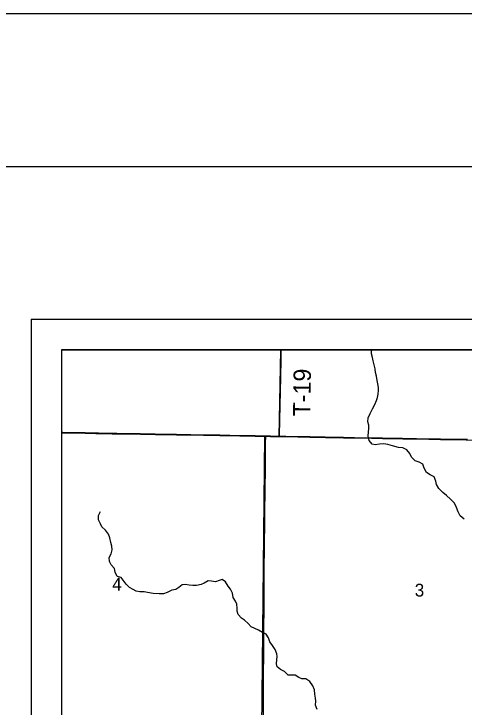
# Model space of a CAD drawing. Extents: x 0 to 34, y 0 to 22.
# Drawn here: x 1.944 to 3.417, y 19.729 to 22 of the extents above; entities that cross this region are included whole.
import ezdxf

# ---------------------------------------------------------------- set-up
doc = ezdxf.new("R2010")
doc.units = 0
for name, color, linetype in [('GM_X_Corporation', 7, 'Continuous'), ('GM_X_County_Road', 7, 'Continuous'), ('GM_X_Minor_River', 7, 'Continuous'), ('GM_X_Section_Text', 7, 'Continuous'), ('GM_X_Township_Road', 7, 'Continuous'), ('GM_X_Township_Road_Text', 7, 'Continuous'), ('SH_Border', 7, 'Continuous'), ('SH_Cut_Line', 7, 'Continuous'), ('SH_Data', 7, 'Continuous')]:
    doc.layers.add(name, color=color, linetype=linetype)

msp = doc.modelspace()

# ---------------------------------------------------------------- linework, layer by layer
at = {"layer": 'GM_X_Corporation'}
for points in [[(8.9, 20.9), (2.1, 20.9), (2.1, 14.6217)], [(5.8292, 20.9), (2.1, 20.9), (2.1, 20.6285), (2.1044, 20.6284), (2.1771, 20.6273), (2.2119, 20.6266), (2.2647, 20.6256), (2.3027, 20.6249), (2.3574, 20.6241), (2.4065, 20.6233), (2.4755, 20.6222), (2.5209, 20.6212), (2.5638, 20.6206), (2.6178, 20.6196), (2.6831, 20.6184), (2.7328, 20.6177), (2.7675, 20.617), (2.7831, 20.6167), (2.8132, 20.6163), (2.8341, 20.616), (2.8727, 20.6152), (2.9124, 20.6145), (2.9628, 20.6136), (3.0218, 20.6125), (3.0585, 20.6118), (3.1138, 20.6107), (3.1499, 20.6101), (3.2158, 20.6091), (3.2611, 20.6084), (3.3078, 20.6075), (3.3395, 20.6068), (3.3867, 20.6062), (3.4277, 20.6055)], [(3.4277, 20.6055), (3.3867, 20.6062), (3.3395, 20.6068), (3.3078, 20.6075), (3.2611, 20.6084), (3.2158, 20.6091), (3.1499, 20.6101), (3.1138, 20.6107), (3.0585, 20.6118), (3.0218, 20.6125), (2.9628, 20.6136), (2.9124, 20.6145), (2.8727, 20.6152), (2.8341, 20.616), (2.8132, 20.6163), (2.7831, 20.6167), (2.7675, 20.617), (2.7328, 20.6177), (2.6831, 20.6184), (2.6178, 20.6196), (2.5638, 20.6206), (2.5209, 20.6212), (2.4755, 20.6222), (2.4065, 20.6233), (2.3574, 20.6241), (2.3027, 20.6249), (2.2647, 20.6256), (2.2119, 20.6266), (2.1771, 20.6273), (2.1044, 20.6284), (2.1, 20.6285), (2.1, 14.6217)]]:
    msp.add_lwpolyline(points, dxfattribs=at)
for points in [[(2.8176, 20.9), (2.1, 20.9), (2.1, 20.6286), (2.7647, 20.6164), (2.8121, 20.6157)], [(3.8162, 20.9), (2.8176, 20.9), (2.8121, 20.6157), (3.7914, 20.5987), (3.8107, 20.5986)], [(2.1, 20.6286), (2.1, 19.6632), (2.7554, 19.6589), (2.7647, 20.6164)], [(2.7647, 20.6164), (2.8121, 20.6157), (3.7914, 20.5987), (3.7742, 19.6197), (2.7554, 19.6589)]]:
    msp.add_lwpolyline(points, close=True, dxfattribs=at)
at = {"layer": 'GM_X_County_Road'}
for points in [[(2.8134, 20.6157), (2.8134, 20.6188), (2.8132, 20.6347), (2.814, 20.6689), (2.8151, 20.7186), (2.8158, 20.7621), (2.8171, 20.8112), (2.8182, 20.8671), (2.8189, 20.9)], [(2.1, 20.628), (2.1046, 20.6279), (2.1773, 20.6267), (2.2122, 20.6261), (2.265, 20.625), (2.3029, 20.6244), (2.3576, 20.6236), (2.4067, 20.6228), (2.4757, 20.6216), (2.5211, 20.6207), (2.564, 20.6201), (2.6181, 20.619), (2.6833, 20.6179), (2.7331, 20.6171), (2.7677, 20.6165)], [(2.7597, 19.6587), (2.7598, 19.6611), (2.7601, 19.7052), (2.7604, 19.7412), (2.7604, 19.768), (2.761, 19.8127), (2.7619, 19.9271), (2.7619, 19.9619), (2.7621, 20.0017), (2.7623, 20.0371), (2.763, 20.1241), (2.7632, 20.2012), (2.7637, 20.2329), (2.7639, 20.2584), (2.7642, 20.2808), (2.7646, 20.3143), (2.7652, 20.3616), (2.766, 20.4449), (2.7667, 20.5083), (2.7673, 20.5692), (2.7675, 20.596), (2.7677, 20.615), (2.7677, 20.6165)], [(2.7677, 20.6165), (2.7834, 20.6162), (2.8134, 20.6157)], [(2.8134, 20.6157), (2.8344, 20.6154), (2.8729, 20.6147), (2.9127, 20.614), (2.963, 20.613), (3.0221, 20.6119), (3.0587, 20.6113), (3.1141, 20.6101), (3.1501, 20.6096), (3.216, 20.6086), (3.2614, 20.6078), (3.308, 20.6069), (3.3397, 20.6062), (3.3869, 20.6056), (3.428, 20.605), (3.4646, 20.6042), (3.4994, 20.6037), (3.5771, 20.6023), (3.6406, 20.6013), (3.6915, 20.6002), (3.7549, 20.5993), (3.7946, 20.5986)]]:
    msp.add_lwpolyline(points, dxfattribs=at)
at = {"layer": 'GM_X_Minor_River'}
for points in [[(3.1825, 20.5848), (3.1678, 20.5896), (3.1538, 20.5922), (3.1397, 20.5902), (3.126, 20.589), (3.1162, 20.5911), (3.1058, 20.6031), (3.1035, 20.6169), (3.1045, 20.6309), (3.1051, 20.6404), (3.105, 20.6533), (3.1019, 20.6636), (3.1029, 20.6773), (3.1097, 20.6912), (3.1172, 20.7062), (3.1244, 20.7201), (3.1304, 20.734), (3.134, 20.7438), (3.1357, 20.7544), (3.1368, 20.7673), (3.1366, 20.7768), (3.135, 20.7882), (3.1325, 20.7993), (3.1298, 20.8138), (3.127, 20.8252), (3.1258, 20.837), (3.1227, 20.8504), (3.1195, 20.8641), (3.1175, 20.8744), (3.1136, 20.8867), (3.1134, 20.8962), (3.1158, 20.9)], [(3.4171, 20.3448), (3.4041, 20.3554), (3.3972, 20.3688), (3.3918, 20.383), (3.385, 20.3969), (3.372, 20.4101), (3.359, 20.4222), (3.3468, 20.4328), (3.3346, 20.446), (3.3265, 20.4591), (3.3241, 20.4698), (3.3192, 20.484), (3.3064, 20.4904), (3.2941, 20.4979), (3.2865, 20.5126), (3.2815, 20.5248), (3.2703, 20.5316), (3.2571, 20.5357), (3.2452, 20.5485), (3.2391, 20.5601), (3.2291, 20.5725), (3.216, 20.5789), (3.202, 20.5796), (3.1825, 20.5848)], [(2.9361, 19.7211), (2.9311, 19.7357), (2.9322, 19.7493), (2.9308, 19.7588), (2.9285, 19.7714), (2.9273, 19.7855), (2.9222, 19.7989), (2.9119, 19.8136), (2.8992, 19.8222), (2.8863, 19.8217), (2.8761, 19.8261), (2.8642, 19.8344), (2.8543, 19.8342), (2.8418, 19.8345), (2.8295, 19.8458), (2.8167, 19.8525), (2.8048, 19.8611), (2.8031, 19.8714), (2.8041, 19.8851), (2.8051, 19.8949), (2.8042, 19.9044), (2.7992, 19.9186), (2.79, 19.9317), (2.7811, 19.9437), (2.7765, 19.9563), (2.7691, 19.9679), (2.7575, 19.9738), (2.7444, 19.9813), (2.7207, 19.9925), (2.7099, 20.003), (2.6988, 20.0139), (2.6883, 20.0205), (2.6772, 20.0333), (2.6747, 20.044), (2.6742, 20.0539), (2.6733, 20.0665), (2.6694, 20.076), (2.6613, 20.0887), (2.6589, 20.1025), (2.6524, 20.1159), (2.6446, 20.1256), (2.6358, 20.1394), (2.6254, 20.1477), (2.6154, 20.1445), (2.6032, 20.1394), (2.5899, 20.142), (2.5793, 20.143), (2.5659, 20.1349), (2.5563, 20.1313), (2.5418, 20.1278), (2.5293, 20.1281), (2.5175, 20.1291), (2.505, 20.1309), (2.494, 20.1297), (2.4832, 20.1212), (2.4735, 20.1145), (2.4606, 20.1125), (2.4452, 20.1045), (2.4333, 20.1002), (2.4189, 20.1009), (2.3992, 20.1014), (2.3814, 20.1052), (2.3697, 20.1073), (2.3564, 20.1072), (2.3443, 20.1094), (2.3338, 20.1142), (2.3222, 20.1217), (2.311, 20.1325), (2.3018, 20.1449), (2.2948, 20.1545), (2.282, 20.1575), (2.2754, 20.1709), (2.2727, 20.1835), (2.2623, 20.1951), (2.2568, 20.2067), (2.2556, 20.2196), (2.2619, 20.2316), (2.2656, 20.2444), (2.2644, 20.2566), (2.2612, 20.2689), (2.2574, 20.2834), (2.2531, 20.296), (2.2439, 20.3091), (2.2312, 20.3204), (2.2269, 20.33), (2.2207, 20.3427), (2.2207, 20.3571), (2.227, 20.3706)]]:
    msp.add_lwpolyline(points, dxfattribs=at)
at = {"layer": 'GM_X_Township_Road'}
for points in [[(2.8134, 20.6157), (2.8134, 20.6188), (2.8132, 20.6347), (2.814, 20.6689), (2.8151, 20.7186), (2.8158, 20.7621), (2.8171, 20.8112), (2.8182, 20.8671), (2.8189, 20.9)], [(2.7597, 19.6587), (2.7598, 19.6611), (2.7601, 19.7052), (2.7604, 19.7412), (2.7604, 19.768), (2.761, 19.8127), (2.7619, 19.9271), (2.7619, 19.9619), (2.7621, 20.0017), (2.7623, 20.0371), (2.763, 20.1241), (2.7632, 20.2012), (2.7637, 20.2329), (2.7639, 20.2584), (2.7642, 20.2808), (2.7646, 20.3143), (2.7652, 20.3616), (2.766, 20.4449), (2.7667, 20.5083), (2.7673, 20.5692), (2.7675, 20.596), (2.7677, 20.615), (2.7677, 20.6165)], [(2.7677, 20.6165), (2.7834, 20.6162), (2.8134, 20.6157)]]:
    msp.add_lwpolyline(points, dxfattribs=at)
at = {"layer": 'SH_Border'}
msp.add_lwpolyline([(1.5, 21.5), (33.5, 21.5), (33.5, 0.5), (1.5, 0.5)], close=True, dxfattribs=at)
at = {"layer": 'SH_Cut_Line'}
msp.add_lwpolyline([(0, 0), (34, 0), (34, 22), (0, 22)], close=True, dxfattribs=at)
at = {"layer": 'SH_Data'}
for p, q in [((2, 21), (9, 21)), ((2, 21), (2, 14)), ((2.1, 20.9), (2.1, 14.1)), ((2.1, 20.9), (8.9, 20.9))]:
    msp.add_line(p, q, dxfattribs=at)

# ---------------------------------------------------------------- texts
at = {"layer": 'GM_X_Section_Text'}
for s, p in [('4', (2.2654, 20.1111)), ('3', (3.2554, 20.0917))]:
    msp.add_text(s, height=0.0419, rotation=0, dxfattribs=at).set_placement(p)
at = {"layer": 'GM_X_Township_Road_Text'}
msp.add_text('T-19', height=0.05682, rotation=89.2903, dxfattribs=at).set_placement((2.914, 20.6814))

doc.saveas('drawing.dxf')
